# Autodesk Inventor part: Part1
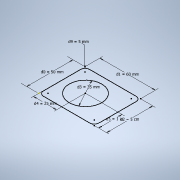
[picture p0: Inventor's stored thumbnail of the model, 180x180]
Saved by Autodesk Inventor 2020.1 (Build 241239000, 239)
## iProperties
Created: 2019-09
Part Number: Part1
Material: Generic
Document SubType Name: Modeling
Designer: Synergysoft Dell02
Density: 1 g/cm^3
Appearance: Default
Author: Synergysoft Dell02
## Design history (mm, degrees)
sketch "Sketch1"
  geometry: L1 (0, -5)-(0, -45); L2 (-5, -50)-(-55, -50); L3 (-60, -45)-(-60, -5); L4 (-55, 0)-(-5, 0); C1 r 17.5 at (-25, -25.4); A1 r 5 centre (-5, -45) between (-5, -50) and (0, -45); A2 r 5 centre (-55, -45) between (-60, -45) and (-55, -50); A3 r 5 centre (-5, -5) between (0, -5) and (-5, 0); A4 r 5 centre (-55, -5) between (-55, 0) and (-60, -5); 4 further points
  constraints: 8 end point, 8 point on circle, 8 point on line, 8 tangent, 5 centre point, 3 equal radius, 2 perpendicular, 1 vertical
  dimensions: "d0" = 50 distance of point (0, 0) point (0, -50); "d1" = 60 distance of point (0, -50) point (-60, -50); "d2" = 50 distance of point (-60, -50) point (-60, 0); "d3" = 35 diameter of C1; "d4" = 25 distance from line of C1.centre L1; "d5" = 25.4 distance from line of C1.centre L4; "d9" = 5 radius of A1
